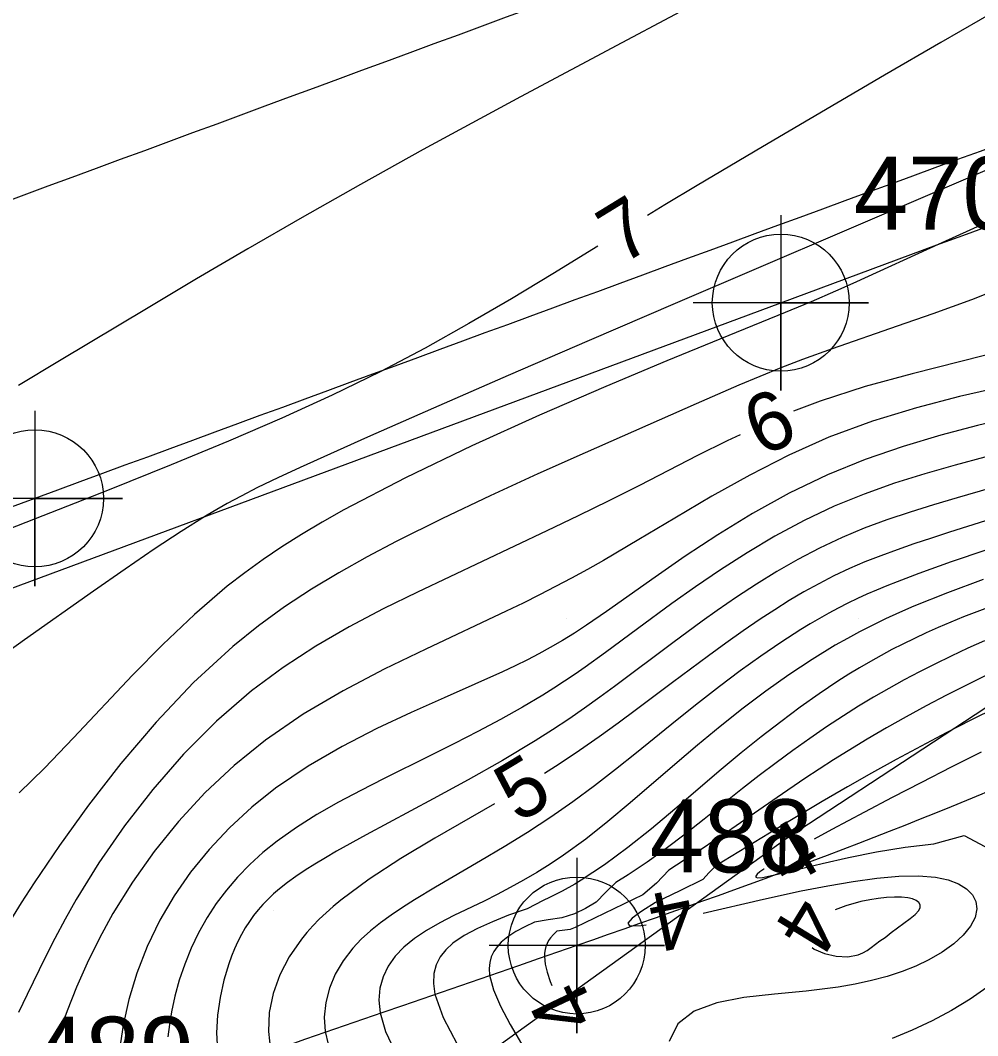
# Model space of a CAD drawing. Extents: x 2602990 to 2605851, y 618069 to 619180.
# Drawn here: x 2603621.32 to 2603654.09, y 618495.72 to 618530.46 of the extents above; entities that cross this region are included whole.
import ezdxf

# ---------------------------------------------------------------- set-up
doc = ezdxf.new("R2010")
doc.units = 0
for name, color, linetype in [('DTM Contours Major', 7, 'Continuous'), ('DTM Contours Major Text', 7, 'Continuous'), ('DTM Contours Minor', 7, 'Continuous'), ('DTM Contours Minor Text', 7, 'Continuous'), ('Exist DTM Breakline', 7, 'Continuous'), ('Exist DTM Breakline Cogo Number', 7, 'Continuous'), ('Exist DTM Breakline Cogo Point CELL', 7, 'Continuous'), ('Exist DTM Crownline', 7, 'Continuous'), ('Exist DTM QL2 LIDAR Elevation Point', 7, 'Continuous'), ('Exist Roads EOP', 7, 'Continuous'), ('Exist Roads EOP Cogo Point CELL', 7, 'Continuous'), ('PH Exist DTM Obscure Area', 7, 'Continuous'), ('PH Exist DTM Obscure Area Text', 7, 'Continuous')]:
    doc.layers.add(name, color=color, linetype=linetype)

# ---------------------------------------------------------------- blocks, each defined once
blk = doc.blocks.new('EXIST DTM BREAKLINE COGO POINT')
at = {"layer": 'Exist DTM Breakline Cogo Point CELL'}
blk.add_lwpolyline([(0, 0.06), (0, -0.06), (0, 0), (0.06, 0), (-0.06, 0)], dxfattribs=at)
blk.add_circle((0, 0), 0.04688, dxfattribs=at)
blk = doc.blocks.new('EXIST ROADS EOP COGO POINT')
at = {"layer": 'Exist Roads EOP Cogo Point CELL'}
blk.add_lwpolyline([(0, 0.06), (0, -0.06), (0, 0), (0.06, 0), (-0.06, 0)], dxfattribs=at)
blk.add_circle((0, 0), 0.04688, dxfattribs=at)

msp = doc.modelspace()

# ---------------------------------------------------------------- linework, layer by layer
at = {"layer": 'DTM Contours Major'}
for points in [[(2603655.14, 618519.195), (2603651.847, 618518.372), (2603650.244, 618517.932), (2603648.704, 618517.437), (2603647.786, 618517.087)], [(2603645.956, 618516.282), (2603645.513, 618516.073), (2603644.506, 618515.57), (2603642.515, 618514.547), (2603641.469, 618514.023), (2603640.413, 618513.506), (2603639.346, 618512.994), (2603634.914, 618510.899), (2603633.746, 618510.323), (2603632.583, 618509.711), (2603631.437, 618509.048), (2603630.317, 618508.322), (2603629.234, 618507.519), (2603628.035, 618506.482), (2603626.905, 618505.348), (2603625.853, 618504.145), (2603624.885, 618502.898), (2603624.01, 618501.633), (2603623.234, 618500.376), (2603622.855, 618499.705), (2603622.503, 618499.044), (2603622.172, 618498.393), (2603621.553, 618497.126), (2603621.254, 618496.511)], [(2603654.467, 618508.087), (2603653.726, 618507.722), (2603653.027, 618507.366), (2603652.333, 618507.002), (2603651.646, 618506.629), (2603650.969, 618506.249), (2603650.305, 618505.862), (2603649.654, 618505.469), (2603649.154, 618505.156), (2603648.663, 618504.839), (2603648.179, 618504.52), (2603647.224, 618503.873), (2603645.671, 618502.796), (2603645.13, 618502.428), (2603644.587, 618502.069), (2603644.042, 618501.724), (2603643.515, 618501.383), (2603643.102, 618500.942), (2603642.624, 618500.54), (2603640.31, 618499.421), (2603640.141, 618499.357), (2603639.685, 618499.29), (2603639.566, 618499.185), (2603639.465, 618499.065), (2603639.402, 618498.971), (2603639.351, 618498.873), (2603639.311, 618498.77), (2603639.282, 618498.662), (2603639.266, 618498.547), (2603639.262, 618498.425), (2603639.288, 618498.171), (2603639.357, 618497.888), (2603639.463, 618497.577), (2603639.52, 618497.438)], [(2603650.92, 618499.08), (2603651.126, 618499.247), (2603651.781, 618499.725), (2603651.952, 618499.869), (2603652.072, 618500), (2603652.124, 618500.107), (2603652.124, 618500.201), (2603652.076, 618500.281), (2603651.987, 618500.348), (2603651.86, 618500.4), (2603651.702, 618500.437), (2603651.486, 618500.461), (2603651.241, 618500.464), (2603650.973, 618500.45), (2603650.689, 618500.418), (2603650.395, 618500.369), (2603650.097, 618500.306), (2603649.578, 618500.16), (2603649.212, 618500.022)], [(2603648.423, 618498.732), (2603648.497, 618498.677), (2603648.851, 618498.526), (2603649.251, 618498.434), (2603649.65, 618498.415), (2603650, 618498.486), (2603650.158, 618498.551), (2603650.304, 618498.635), (2603650.446, 618498.733), (2603650.746, 618498.959), (2603650.92, 618499.08)]]:
    msp.add_lwpolyline(points, dxfattribs=at)
at = {"layer": 'DTM Contours Minor'}
for points in [[(2603687.101, 618547.534), (2603683.832, 618545.986), (2603681.29, 618544.767), (2603678.745, 618543.527), (2603677.445, 618542.886), (2603674.873, 618541.603), (2603672.216, 618540.257), (2603669.508, 618538.863), (2603666.782, 618537.438), (2603664.073, 618535.996), (2603661.414, 618534.554), (2603659.152, 618533.303), (2603656.962, 618532.072), (2603654.853, 618530.869), (2603652.831, 618529.704), (2603650.906, 618528.585), (2603646.722, 618526.134), (2603644.485, 618524.807), (2603643.386, 618524.146), (2603642.793, 618523.785)], [(2603648.436, 618533.174), (2603641.905, 618529.698), (2603638.437, 618527.844), (2603635.115, 618526.039), (2603632.965, 618524.846), (2603630.969, 618523.716), (2603629.107, 618522.642), (2603627.355, 618521.617), (2603625.693, 618520.631), (2603622.663, 618518.817), (2603621.257, 618517.968)], [(2603655.076, 618525.638), (2603652.375, 618524.468), (2603643.731, 618520.774), (2603640.797, 618519.511), (2603638.016, 618518.308), (2603635.461, 618517.193), (2603633.206, 618516.199), (2603630.901, 618515.164), (2603630.133, 618514.808), (2603629.443, 618514.475), (2603628.878, 618514.186), (2603628.399, 618513.927), (2603627.911, 618513.646), (2603627.657, 618513.494), (2603626.826, 618512.971), (2603625.907, 618512.363), (2603624.906, 618511.679), (2603623.828, 618510.928), (2603621.469, 618509.259), (2603619.616, 618507.937)], [(2603655.265, 618523.933), (2603652.863, 618522.849), (2603649.816, 618521.458), (2603649.23, 618521.196), (2603648.395, 618520.835), (2603647.249, 618520.361), (2603645.27, 618519.556), (2603643.455, 618518.811), (2603641.36, 618517.934), (2603639.096, 618516.955), (2603636.774, 618515.904), (2603634.504, 618514.812), (2603632.396, 618513.709), (2603631.654, 618513.289), (2603630.948, 618512.869), (2603630.274, 618512.443), (2603629.629, 618512.008), (2603629.007, 618511.56), (2603628.407, 618511.096), (2603627.278, 618510.132), (2603626.201, 618509.11), (2603625.161, 618508.052), (2603623.147, 618505.914), (2603622.146, 618504.878), (2603621.286, 618504.029)], [(2603641.088, 618522.741), (2603639.544, 618521.793), (2603638.129, 618520.938), (2603636.676, 618520.087), (2603635.18, 618519.25), (2603633.635, 618518.436), (2603631.998, 618517.634), (2603630.278, 618516.848), (2603628.449, 618516.059), (2603626.487, 618515.25), (2603624.365, 618514.401), (2603618.33, 618512.036)], [(2603655.296, 618521.453), (2603653.877, 618520.905), (2603652.561, 618520.424), (2603651.336, 618519.995), (2603649.114, 618519.227), (2603648.093, 618518.857), (2603647.355, 618518.572), (2603646.632, 618518.279), (2603645.915, 618517.977), (2603644.459, 618517.342), (2603640.655, 618515.666), (2603639.039, 618514.943), (2603637.402, 618514.192), (2603635.775, 618513.417), (2603634.19, 618512.625), (2603633.194, 618512.101), (2603632.227, 618511.562), (2603631.285, 618510.996), (2603630.368, 618510.393), (2603629.473, 618509.745), (2603628.596, 618509.038), (2603627.253, 618507.799), (2603625.97, 618506.445), (2603624.766, 618505.03), (2603623.657, 618503.606), (2603622.661, 618502.228), (2603621.796, 618500.948), (2603621.354, 618500.261), (2603620.33, 618498.63)], [(2603654.887, 618517.912), (2603653.473, 618517.589), (2603651.994, 618517.206), (2603650.49, 618516.747), (2603648.999, 618516.199), (2603647.623, 618515.586), (2603646.288, 618514.905), (2603644.991, 618514.179), (2603643.727, 618513.433), (2603642.491, 618512.693), (2603641.28, 618511.983), (2603640.733, 618511.675), (2603640.188, 618511.377), (2603639.64, 618511.087), (2603639.088, 618510.803), (2603638.528, 618510.523), (2603637.957, 618510.245), (2603635.197, 618508.95), (2603633.779, 618508.262), (2603632.373, 618507.524), (2603631.007, 618506.719), (2603629.71, 618505.83), (2603628.641, 618504.966), (2603627.649, 618504.036), (2603626.737, 618503.052), (2603625.905, 618502.026), (2603625.157, 618500.972), (2603624.493, 618499.901), (2603624.028, 618499.05), (2603623.615, 618498.205), (2603623.248, 618497.375), (2603622.925, 618496.567), (2603622.642, 618495.79), (2603622.396, 618495.053)], [(2603655.279, 618516.887), (2603654.089, 618516.599), (2603652.834, 618516.268), (2603651.542, 618515.883), (2603650.237, 618515.435), (2603648.946, 618514.912), (2603647.64, 618514.282), (2603646.387, 618513.588), (2603645.198, 618512.86), (2603644.083, 618512.124), (2603643.054, 618511.412), (2603641.385, 618510.231), (2603640.704, 618509.766), (2603640.29, 618509.496), (2603639.878, 618509.242), (2603639.459, 618508.999), (2603639.075, 618508.789), (2603638.676, 618508.583), (2603638.26, 618508.377), (2603637.823, 618508.171), (2603636.879, 618507.744), (2603635.829, 618507.283), (2603634.699, 618506.781), (2603633.523, 618506.227), (2603632.335, 618505.615), (2603631.17, 618504.938), (2603630.061, 618504.186), (2603629.241, 618503.533), (2603628.48, 618502.833), (2603627.783, 618502.092), (2603627.152, 618501.314), (2603626.589, 618500.504), (2603626.098, 618499.667), (2603625.663, 618498.768), (2603625.309, 618497.861), (2603625.034, 618496.96), (2603624.838, 618496.082), (2603624.72, 618495.24)], [(2603654.331, 618515.517), (2603653.317, 618515.246), (2603652.283, 618514.95), (2603651.239, 618514.622), (2603650.201, 618514.254), (2603649.18, 618513.838), (2603648.147, 618513.349), (2603647.152, 618512.813), (2603646.198, 618512.247), (2603645.29, 618511.663), (2603644.431, 618511.078), (2603643.627, 618510.506), (2603642.447, 618509.639), (2603641.346, 618508.826), (2603640.659, 618508.332), (2603640.309, 618508.09), (2603639.953, 618507.85), (2603639.588, 618507.612), (2603639.21, 618507.375), (2603638.505, 618506.956), (2603637.76, 618506.54), (2603636.984, 618506.126), (2603636.184, 618505.714), (2603635.366, 618505.303), (2603633.752, 618504.504), (2603632.973, 618504.109), (2603632.21, 618503.705), (2603631.472, 618503.285), (2603630.769, 618502.845), (2603630.111, 618502.378), (2603629.626, 618501.987), (2603629.174, 618501.576), (2603628.757, 618501.148), (2603628.374, 618500.701), (2603628.026, 618500.238), (2603627.712, 618499.759), (2603627.421, 618499.241), (2603627.166, 618498.709), (2603626.947, 618498.169), (2603626.763, 618497.623), (2603626.612, 618497.076), (2603626.494, 618496.531), (2603626.423, 618496.1), (2603626.374, 618495.674)], [(2603656.029, 618514.891), (2603653.393, 618514.128), (2603652.582, 618513.888), (2603651.777, 618513.637), (2603650.984, 618513.371), (2603650.206, 618513.082), (2603649.447, 618512.767), (2603648.68, 618512.406), (2603647.937, 618512.016), (2603647.216, 618511.601), (2603646.517, 618511.168), (2603645.839, 618510.721), (2603645.179, 618510.265), (2603644.666, 618509.9), (2603643.661, 618509.162), (2603641.659, 618507.666), (2603641.155, 618507.298), (2603640.636, 618506.928), (2603640.096, 618506.555), (2603639.534, 618506.181), (2603638.944, 618505.806), (2603637.828, 618505.138), (2603636.653, 618504.477), (2603635.458, 618503.828), (2603633.164, 618502.596), (2603632.142, 618502.028), (2603631.762, 618501.808), (2603631.405, 618501.593), (2603631.069, 618501.38), (2603630.755, 618501.169), (2603630.463, 618500.957), (2603630.191, 618500.743), (2603629.99, 618500.569), (2603629.802, 618500.392), (2603629.626, 618500.21), (2603629.461, 618500.022), (2603629.306, 618499.828), (2603629.162, 618499.627), (2603629.021, 618499.408), (2603628.89, 618499.18), (2603628.768, 618498.943), (2603628.655, 618498.696), (2603628.551, 618498.44), (2603628.455, 618498.174), (2603628.287, 618497.616), (2603628.158, 618497.03), (2603628.073, 618496.426), (2603628.042, 618495.817), (2603628.07, 618495.213)], [(2603655.186, 618513.597), (2603653.121, 618512.945), (2603652.507, 618512.746), (2603651.91, 618512.549), (2603651.333, 618512.348), (2603650.772, 618512.142), (2603650.229, 618511.928), (2603649.701, 618511.702), (2603649.168, 618511.45), (2603648.649, 618511.184), (2603648.141, 618510.902), (2603647.64, 618510.605), (2603647.143, 618510.294), (2603646.648, 618509.969), (2603646.061, 618509.569), (2603645.47, 618509.152), (2603644.872, 618508.718), (2603643.65, 618507.81), (2603642.411, 618506.881), (2603641.785, 618506.418), (2603641.138, 618505.949), (2603640.466, 618505.478), (2603639.765, 618505.007), (2603639.262, 618504.685)], [(2603654.367, 618512.333), (2603653.186, 618511.93), (2603652.079, 618511.535), (2603651.332, 618511.252), (2603650.978, 618511.111), (2603650.633, 618510.968), (2603650.299, 618510.823), (2603649.973, 618510.674), (2603649.641, 618510.514), (2603649.315, 618510.349), (2603648.993, 618510.177), (2603648.674, 618509.998), (2603648.355, 618509.811), (2603648.035, 618509.615), (2603647.358, 618509.178), (2603646.668, 618508.705), (2603645.966, 618508.199), (2603645.255, 618507.665), (2603644.535, 618507.108), (2603643.808, 618506.53), (2603642.409, 618505.4), (2603641.697, 618504.831), (2603640.973, 618504.269), (2603640.237, 618503.721), (2603639.486, 618503.194), (2603638.686, 618502.673), (2603637.879, 618502.177), (2603637.077, 618501.704), (2603635.532, 618500.804), (2603634.812, 618500.369), (2603634.402, 618500.108), (2603634.012, 618499.846), (2603633.645, 618499.578), (2603633.303, 618499.303), (2603632.989, 618499.016), (2603632.705, 618498.715), (2603632.371, 618498.282), (2603632.102, 618497.823), (2603631.901, 618497.345), (2603631.774, 618496.854), (2603631.725, 618496.357), (2603631.761, 618495.859), (2603631.863, 618495.425)], [(2603654.28, 618511.325), (2603653.06, 618510.873), (2603651.908, 618510.412), (2603651.415, 618510.199), (2603650.939, 618509.983), (2603650.478, 618509.76), (2603650.05, 618509.542), (2603649.63, 618509.315), (2603649.213, 618509.078), (2603648.421, 618508.594), (2603647.631, 618508.07), (2603646.844, 618507.511), (2603646.059, 618506.921), (2603645.278, 618506.303), (2603644.501, 618505.662), (2603643.727, 618505.002), (2603642.191, 618503.681), (2603641.43, 618503.046), (2603640.673, 618502.447), (2603639.919, 618501.898), (2603639.458, 618501.59), (2603639, 618501.303), (2603638.544, 618501.036), (2603638.09, 618500.786), (2603637.641, 618500.55), (2603637.195, 618500.327), (2603636.164, 618499.826), (2603635.679, 618499.577), (2603635.226, 618499.32), (2603634.812, 618499.045), (2603634.446, 618498.745), (2603634.154, 618498.436), (2603633.918, 618498.1), (2603633.742, 618497.737), (2603633.632, 618497.348), (2603633.595, 618496.936), (2603633.636, 618496.501), (2603633.824, 618495.864), (2603634.141, 618495.194)], [(2603654.917, 618510.547), (2603654.058, 618510.225), (2603653.607, 618510.048), (2603653.169, 618509.869), (2603652.744, 618509.688), (2603652.329, 618509.504), (2603651.924, 618509.315), (2603651.526, 618509.121), (2603651.154, 618508.931), (2603650.785, 618508.733), (2603650.417, 618508.527), (2603650.049, 618508.311), (2603649.679, 618508.085), (2603649.305, 618507.846), (2603648.668, 618507.419), (2603648.017, 618506.957), (2603647.354, 618506.464), (2603646.68, 618505.943), (2603645.998, 618505.395), (2603645.31, 618504.825), (2603643.721, 618503.47), (2603642.922, 618502.799), (2603642.121, 618502.157), (2603641.32, 618501.563), (2603640.522, 618501.036), (2603640.304, 618500.906), (2603639.868, 618500.663), (2603639.434, 618500.443), (2603639.218, 618500.341), (2603638.666, 618500.061), (2603638.037, 618499.841), (2603637.483, 618499.615), (2603636.971, 618499.388), (2603636.513, 618499.147), (2603636.123, 618498.88), (2603635.885, 618498.659), (2603635.695, 618498.413), (2603635.558, 618498.141), (2603635.479, 618497.841), (2603635.462, 618497.508), (2603635.511, 618497.142), (2603635.793, 618496.341), (2603636.274, 618495.425)], [(2603654.319, 618509.232), (2603653.749, 618508.975), (2603653.184, 618508.71), (2603652.623, 618508.436), (2603652.095, 618508.168), (2603651.571, 618507.89), (2603651.05, 618507.601), (2603650.53, 618507.302), (2603650.012, 618506.989), (2603649.494, 618506.664), (2603648.919, 618506.286), (2603648.343, 618505.891), (2603647.768, 618505.481), (2603647.192, 618505.058), (2603646.617, 618504.622), (2603646.042, 618504.175), (2603644.729, 618503.131), (2603644.075, 618502.616), (2603643.424, 618502.12), (2603642.776, 618501.652), (2603642.132, 618501.224), (2603641.705, 618500.964), (2603641.347, 618500.621), (2603641.032, 618500.29), (2603640.665, 618500.071), (2603640.285, 618499.884), (2603639.861, 618499.751), (2603639.392, 618499.684), (2603638.926, 618499.603), (2603638.589, 618499.443), (2603638.283, 618499.278), (2603638.012, 618499.104), (2603637.781, 618498.915), (2603637.641, 618498.763), (2603637.527, 618498.598), (2603637.443, 618498.419), (2603637.39, 618498.225), (2603637.371, 618498.014), (2603637.386, 618497.784), (2603637.516, 618497.288), (2603637.757, 618496.725), (2603638.086, 618496.105), (2603638.477, 618495.434)], [(2603654.709, 618506.943), (2603653.861, 618506.518), (2603653.007, 618506.08), (2603652.151, 618505.63), (2603651.299, 618505.172), (2603650.457, 618504.707), (2603649.63, 618504.239), (2603648.763, 618503.734), (2603647.485, 618502.969), (2603645.123, 618501.525), (2603644.899, 618501.298), (2603644.683, 618501.064), (2603643.898, 618500.673), (2603643.067, 618500.272), (2603642.59, 618499.975), (2603642.27, 618499.74), (2603642.117, 618499.57), (2603642.168, 618499.478), (2603642.577, 618499.485), (2603642.742, 618499.513)], [(2603654.208, 618505.418), (2603653.186, 618504.907), (2603652.164, 618504.387), (2603651.167, 618503.872), (2603650.214, 618503.371), (2603649.094, 618502.769), (2603648.497, 618502.438)], [(2603637.548, 618503.654), (2603635.506, 618502.477), (2603634.348, 618501.783), (2603633.263, 618501.077), (2603632.288, 618500.354), (2603632.03, 618500.14), (2603631.786, 618499.923), (2603631.555, 618499.703), (2603631.337, 618499.48), (2603631.132, 618499.252), (2603630.941, 618499.019), (2603630.529, 618498.422), (2603630.206, 618497.8), (2603629.976, 618497.16), (2603629.843, 618496.511), (2603629.812, 618495.861), (2603629.885, 618495.218)], [(2603646.777, 618501.419), (2603646.774, 618501.417), (2603646.639, 618501.32), (2603646.544, 618501.24), (2603646.495, 618501.179), (2603646.498, 618501.139), (2603646.557, 618501.122), (2603646.726, 618501.135), (2603646.99, 618501.184), (2603647.338, 618501.263), (2603648.769, 618501.611), (2603649.669, 618501.817), (2603650.625, 618502.009), (2603651.605, 618502.166), (2603652.586, 618502.286), (2603653.634, 618502.567), (2603654.331, 618502.192)], [(2603644.7, 618499.916), (2603646.762, 618500.389), (2603648.051, 618500.67), (2603648.96, 618500.85), (2603649.827, 618500.999), (2603650.639, 618501.11), (2603651.387, 618501.176), (2603652.06, 618501.19), (2603652.647, 618501.144), (2603653.078, 618501.052), (2603653.434, 618500.917), (2603653.712, 618500.744), (2603653.911, 618500.539), (2603654.029, 618500.307), (2603654.062, 618500.057), (2603654, 618499.765), (2603653.842, 618499.464), (2603653.596, 618499.161), (2603653.271, 618498.863), (2603652.875, 618498.577), (2603652.416, 618498.311), (2603651.977, 618498.102), (2603651.501, 618497.914), (2603650.992, 618497.747), (2603650.455, 618497.601), (2603649.893, 618497.478), (2603649.31, 618497.376), (2603648.221, 618497.244), (2603647.131, 618497.141), (2603646.092, 618497.023), (2603645.16, 618496.845), (2603644.389, 618496.562), (2603643.833, 618496.129), (2603643.53, 618495.516)], [(2603654.52, 618497.451), (2603653.83, 618496.963), (2603653.194, 618496.577), (2603652.531, 618496.225), (2603651.85, 618495.908), (2603651.159, 618495.626)]]:
    msp.add_lwpolyline(points, dxfattribs=at)
at = {"layer": 'Exist DTM Breakline'}
msp.add_line((2603600.378, 618503.371), (2603647.352, 618520.802), dxfattribs=at)
msp.add_spline([(2603647.352, 618520.802), (2603704.337, 618541.966), (2603758.983, 618562.663), (2603811.118, 618582.434), (2603865.604, 618602.567), (2603913.966, 618621.231), (2603963.574, 618640.143), (2603974.725, 618636.355), (2603978.77, 618630.138), (2603971.844, 618627.992), (2603956.88, 618621.982), (2603923.969, 618609.772), (2603877.426, 618591.796), (2603827.273, 618571.857), (2603776.875, 618552.809), (2603720.479, 618530.104), (2603675.109, 618514.176), (2603657.355, 618505.354), (2603640.368, 618498.804), (2603619.191, 618491.366), (2603591.676, 618480.386)], degree=3, dxfattribs=at)
at = {"layer": 'Exist DTM Crownline'}
msp.add_spline([(2603233.488, 618380.754), (2603285.185, 618400.095), (2603335.457, 618418.629), (2603390.812, 618439.069), (2603440.087, 618457.325), (2603493.996, 618477.231), (2603542.655, 618495.301), (2603600.808, 618516.867), (2603653.659, 618536.362), (2603706.222, 618555.742), (2603764.811, 618577.593), (2603823.52, 618599.847), (2603878.564, 618620.56), (2603937.951, 618643.078), (2603997.369, 618665.789), (2604036.209, 618680.665), (2604055.311, 618688.017)], degree=3, dxfattribs=at)
at = {"layer": 'Exist DTM QL2 LIDAR Elevation Point'}
for p, q in [((2603640, 618510), (2603640, 618510)), ((2603650, 618510), (2603650, 618510)), ((2603630, 618500), (2603630, 618500)), ((2603640, 618500), (2603640, 618500)), ((2603650, 618500), (2603650, 618500))]:
    msp.add_line(p, q, dxfattribs=at)
at = {"layer": 'Exist Roads EOP'}
for points in [[(2603230.17, 618389.98), (2603282.929, 618409.597), (2603332.773, 618427.868), (2603388.167, 618448.413), (2603437.203, 618466.721), (2603490.778, 618486.527), (2603539.039, 618504.558), (2603597.451, 618526.156), (2603651.053, 618545.972), (2603705.208, 618566.084), (2603762.02, 618587.183), (2603820.334, 618609.162), (2603876.341, 618629.99), (2603934.909, 618652.28), (2603996.409, 618675.568), (2604033.216, 618689.957), (2604052.01, 618697.199)], [(2604034.633, 618668.486), (2603984.89, 618650.123), (2603936.767, 618631.654), (2603888.195, 618613.335), (2603837.766, 618594.258), (2603782.918, 618573.705), (2603731.939, 618554.39), (2603671.126, 618532.171), (2603621.822, 618514.106), (2603561.545, 618491.877), (2603506.421, 618471.293), (2603452.163, 618451.33), (2603398.364, 618431.316), (2603341.431, 618410.355), (2603281.65, 618388.199), (2603223.033, 618366.475), (2603185.717, 618352.612)]]:
    msp.add_spline(points, degree=3, dxfattribs=at)
at = {"layer": 'PH Exist DTM Obscure Area'}
msp.add_lwpolyline([(2603611.669, 618481.486), (2603621.832, 618487.193), (2603634.854, 618493.342), (2603647.569, 618502.487), (2603662.594, 618512.341), (2603675.88, 618519.311), (2603694.34, 618526.885), (2603713.833, 618527.652), (2603730.339, 618527.158), (2603742.923, 618535.893), (2603753.597, 618544.606), (2603767.139, 618552.942), (2603782.778, 618556.802), (2603798.072, 618555.067), (2603811.904, 618561.907)], dxfattribs=at)

# ---------------------------------------------------------------- block references
at = {"layer": 'Exist DTM Breakline Cogo Point CELL', "xscale": 50, "yscale": 50}
for p in [(2603647.352, 618520.802), (2603640.368, 618498.804)]:
    msp.add_blockref('EXIST DTM BREAKLINE COGO POINT', p, dxfattribs=at)
at = {"layer": 'Exist Roads EOP Cogo Point CELL', "xscale": 50, "yscale": 50}
msp.add_blockref('EXIST ROADS EOP COGO POINT', (2603621.822, 618514.106), dxfattribs=at)

# ---------------------------------------------------------------- texts
at = {"layer": 'DTM Contours Major Text'}
for s, rotation, p in [('6', 23.7262, (2603646.669, 618515.52)), ('4', 238.5273, (2603647.834, 618500.612)), ('4', 115.3758, (2603641.117, 618496.366))]:
    msp.add_text(s, height=2, rotation=rotation, dxfattribs=at).set_placement(p)
at = {"layer": 'DTM Contours Minor Text'}
for s, rotation, p in [('7', 31.4804, (2603641.905, 618522.07)), ('5', 31.0305, (2603638.364, 618502.969)), ('4', 30.6339, (2603647.575, 618500.751)), ('4', 191.6134, (2603644.163, 618500.811))]:
    msp.add_text(s, height=2, rotation=rotation, dxfattribs=at).set_placement(p)
at = {"layer": 'Exist DTM Breakline Cogo Number'}
for s, p in [('470', (2603649.852, 618523.302)), ('488', (2603642.868, 618501.304)), ('489', (2603621.691, 618493.866))]:
    msp.add_text(s, height=2.5, dxfattribs=at).set_placement(p)
at = {"layer": 'PH Exist DTM Obscure Area Text'}
msp.add_text('OBSCURED', height=6, rotation=17.4224, dxfattribs=at).set_placement((2603643.567, 618484.339))

doc.saveas('drawing.dxf')
